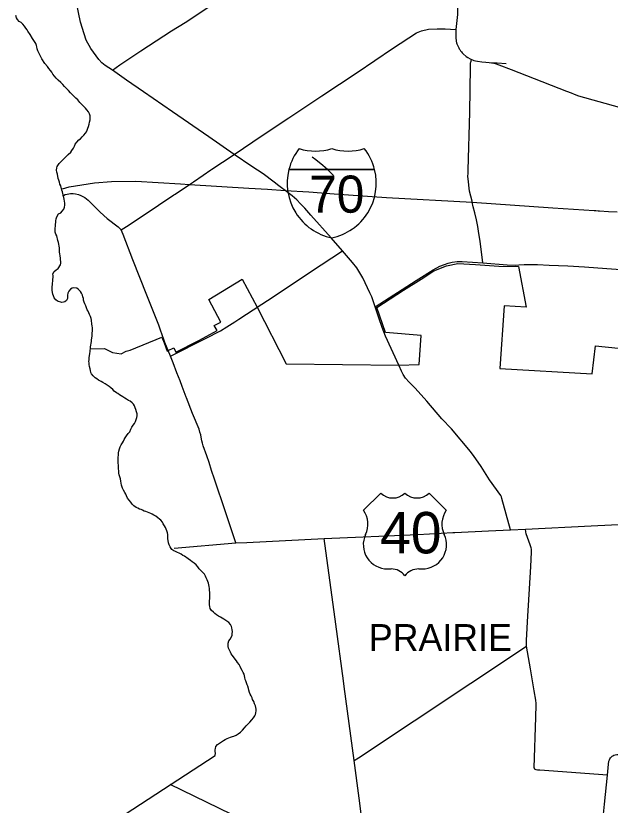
# Model space of a CAD drawing. Extents: x 1755200 to 1902939, y 644115 to 788070.
# Drawn here: x 1756901 to 1776912, y 701476 to 728043 of the extents above; entities that cross this region are included whole.
import ezdxf

# ---------------------------------------------------------------- set-up
doc = ezdxf.new("R2010")
doc.units = 0
for name, color, linetype in [('GM_X_County', 7, 'Continuous'), ('GM_X_County_Road', 7, 'Continuous'), ('GM_X_Interstate_Route', 7, 'Continuous'), ('GM_X_Interstate_Shield', 7, 'Continuous'), ('GM_X_Township', 7, 'Continuous'), ('GM_X_Township_Road', 7, 'Continuous'), ('GM_X_Township_Text', 7, 'Continuous'), ('GM_X_US_Route', 7, 'Continuous'), ('GM_X_US_Shield', 7, 'Continuous')]:
    doc.layers.add(name, color=color, linetype=linetype)

msp = doc.modelspace()

# ---------------------------------------------------------------- linework, layer by layer
at = {"layer": 'GM_X_County'}
msp.add_lwpolyline([(1759102, 700215), (1763614, 703154), (1763629, 703222), (1763617, 703283), (1763616, 703335), (1763624, 703387), (1763640, 703451), (1763691, 703517), (1763762, 703565), (1763830, 703611), (1763897, 703653), (1763952, 703683), (1764018, 703717), (1764071, 703745), (1764125, 703762), (1764195, 703784), (1764246, 703802), (1764320, 703836), (1764391, 703878), (1764462, 703938), (1764529, 704006), (1764599, 704075), (1764662, 704149), (1764719, 704213), (1764784, 704273), (1764848, 704345), (1764905, 704417), (1764948, 704482), (1764966, 704532), (1764983, 704588), (1764989, 704656), (1764993, 704708), (1764986, 704761), (1764968, 704815), (1764934, 704883), (1764909, 704966), (1764875, 705036), (1764859, 705087), (1764825, 705153), (1764796, 705217), (1764768, 705274), (1764746, 705348), (1764732, 705409), (1764713, 705477), (1764691, 705531), (1764669, 705594), (1764641, 705656), (1764626, 705706), (1764606, 705775), (1764602, 705825), (1764585, 705891), (1764557, 705944), (1764521, 706012), (1764477, 706093), (1764449, 706147), (1764420, 706208), (1764368, 706280), (1764330, 706337), (1764290, 706387), (1764228, 706470), (1764190, 706522), (1764156, 706575), (1764125, 706625), (1764091, 706695), (1764065, 706766), (1764053, 706820), (1764046, 706870), (1764050, 706933), (1764077, 707009), (1764113, 707061), (1764160, 707141), (1764180, 707193), (1764189, 707243), (1764193, 707320), (1764186, 707380), (1764174, 707440), (1764160, 707491), (1764132, 707555), (1764072, 707622), (1764008, 707666), (1763904, 707739), (1763854, 707765), (1763790, 707800), (1763724, 707840), (1763656, 707887), (1763602, 707929), (1763552, 707972), (1763490, 708032), (1763444, 708099), (1763428, 708159), (1763421, 708221), (1763421, 708288), (1763423, 708354), (1763428, 708436), (1763430, 708509), (1763433, 708579), (1763429, 708647), (1763424, 708699), (1763418, 708774), (1763410, 708838), (1763387, 708943), (1763367, 709005), (1763347, 709059), (1763314, 709130), (1763290, 709180), (1763250, 709247), (1763198, 709305), (1763146, 709366), (1763078, 709432), (1763028, 709501), (1762974, 709561), (1762910, 709620), (1762844, 709666), (1762778, 709711), (1762706, 709763), (1762580, 709854), (1762528, 709883), (1762468, 709921), (1762400, 709958), (1762346, 709984), (1762277, 710011), (1762227, 710033), (1762157, 710083), (1762134, 710119), (1762101, 710170), (1762068, 710241), (1762046, 710309), (1762028, 710387), (1762023, 710440), (1762021, 710504), (1762017, 710584), (1762006, 710637), (1761984, 710709), (1761964, 710767), (1761938, 710818), (1761903, 710882), (1761865, 710948), (1761839, 710999), (1761787, 711065), (1761735, 711106), (1761683, 711150), (1761613, 711203), (1761543, 711241), (1761493, 711268), (1761443, 711292), (1761392, 711310), (1761340, 711335), (1761274, 711357), (1761224, 711377), (1761172, 711402), (1761118, 711422), (1761064, 711444), (1761013, 711467), (1760949, 711493), (1760879, 711548), (1760821, 711606), (1760775, 711673), (1760715, 711743), (1760666, 711814), (1760630, 711888), (1760600, 711941), (1760570, 711999), (1760522, 712078), (1760489, 712144), (1760463, 712241), (1760447, 712311), (1760438, 712381), (1760424, 712456), (1760402, 712524), (1760383, 712592), (1760371, 712655), (1760365, 712705), (1760362, 712813), (1760360, 712870), (1760359, 712924), (1760353, 712990), (1760349, 713052), (1760352, 713121), (1760352, 713187), (1760357, 713261), (1760361, 713333), (1760371, 713392), (1760394, 713464), (1760415, 713534), (1760449, 713602), (1760490, 713674), (1760524, 713728), (1760553, 713780), (1760587, 713836), (1760628, 713908), (1760689, 713986), (1760739, 714046), (1760774, 714126), (1760813, 714195), (1760851, 714265), (1760892, 714317), (1760930, 714393), (1760957, 714453), (1760980, 714523), (1760984, 714585), (1760982, 714647), (1760969, 714720), (1760943, 714788), (1760923, 714853), (1760902, 714911), (1760861, 714970), (1760820, 715018), (1760750, 715068), (1760691, 715099), (1760623, 715141), (1760573, 715171), (1760503, 715218), (1760453, 715254), (1760393, 715291), (1760341, 715327), (1760291, 715352), (1760217, 715414), (1760165, 715465), (1760097, 715527), (1760045, 715566), (1759979, 715614), (1759908, 715655), (1759836, 715697), (1759770, 715737), (1759686, 715784), (1759624, 715827), (1759574, 715859), (1759502, 715923), (1759450, 715990), (1759426, 716042), (1759412, 716103), (1759401, 716163), (1759387, 716235), (1759373, 716302), (1759366, 716358), (1759364, 716412), (1759366, 716468), (1759375, 716540), (1759385, 716599), (1759398, 716677), (1759404, 716741), (1759409, 716793), (1759413, 716829), (1759415, 716843), (1759421, 716902), (1759430, 716954), (1759438, 717020), (1759446, 717080), (1759453, 717140), (1759461, 717199), (1759470, 717269), (1759472, 717325), (1759476, 717377), (1759479, 717429), (1759481, 717482), (1759479, 717540), (1759474, 717604), (1759466, 717662), (1759447, 717795), (1759435, 717861), (1759421, 717921), (1759388, 717992), (1759358, 718046), (1759332, 718099), (1759308, 718149), (1759280, 718215), (1759257, 718280), (1759227, 718348), (1759203, 718406), (1759185, 718475), (1759176, 718525), (1759158, 718589), (1759144, 718640), (1759110, 718712), (1759082, 718762), (1759017, 718835), (1758954, 718879), (1758850, 718888), (1758798, 718872), (1758747, 718844), (1758684, 718774), (1758658, 718712), (1758647, 718638), (1758647, 718586), (1758647, 718534), (1758609, 718457), (1758556, 718416), (1758505, 718403), (1758446, 718392), (1758310, 718440), (1758246, 718485), (1758197, 718550), (1758166, 718615), (1758143, 718677), (1758136, 718734), (1758125, 718804), (1758126, 718858), (1758129, 718926), (1758134, 718995), (1758139, 719047), (1758144, 719113), (1758151, 719183), (1758158, 719233), (1758161, 719295), (1758152, 719364), (1758191, 719435), (1758262, 719497), (1758329, 719540), (1758402, 719659), (1758412, 719713), (1758413, 719767), (1758411, 719836), (1758405, 719890), (1758392, 719966), (1758382, 720032), (1758376, 720089), (1758369, 720189), (1758367, 720239), (1758362, 720294), (1758350, 720360), (1758338, 720410), (1758316, 720478), (1758278, 720632), (1758249, 720699), (1758230, 720764), (1758227, 720830), (1758228, 720896), (1758235, 720964), (1758242, 721030), (1758249, 721081), (1758254, 721145), (1758261, 721211), (1758280, 721277), (1758339, 721373), (1758416, 721408), (1758464, 721473), (1758513, 721533), (1758541, 721597), (1758551, 721667), (1758551, 721737), (1758541, 721808), (1758533, 721866), (1758523, 721922), (1758501, 721990), (1758497, 722012), (1758483, 722064), (1758471, 722123), (1758452, 722179), (1758441, 722219), (1758412, 722319), (1758388, 722379), (1758374, 722445), (1758352, 722512), (1758330, 722572), (1758309, 722714), (1758284, 722778), (1758277, 722849), (1758280, 722921), (1758297, 722975), (1758364, 723076), (1758425, 723140), (1758483, 723200), (1758538, 723246), (1758609, 723314), (1758669, 723376), (1758750, 723448), (1758793, 723508), (1758842, 723584), (1758878, 723652), (1758905, 723718), (1758954, 723794), (1759024, 723866), (1759075, 723906), (1759140, 723968), (1759188, 724020), (1759249, 724088), (1759277, 724140), (1759304, 724192), (1759330, 724258), (1759351, 724322), (1759373, 724400), (1759388, 724468), (1759400, 724539), (1759407, 724625), (1759401, 724677), (1759385, 724743), (1759350, 724812), (1759288, 724874), (1759246, 724929), (1759178, 724999), (1759114, 725070), (1759052, 725130), (1758986, 725209), (1758926, 725270), (1758856, 725342), (1758804, 725399), (1758746, 725453), (1758676, 725526), (1758608, 725600), (1758544, 725659), (1758480, 725725), (1758416, 725802), (1758327, 725881), (1758262, 725942), (1758205, 726013), (1758152, 726080), (1758115, 726141), (1758068, 726206), (1758015, 726273), (1757963, 726333), (1757884, 726434), (1757777, 726589), (1757719, 726711), (1757643, 726864), (1757621, 726934), (1757614, 726993), (1757601, 727043), (1757573, 727111), (1757532, 727178), (1757462, 727283), (1757389, 727408), (1757310, 727522), (1757280, 727574), (1757243, 727626), (1757194, 727695), (1757135, 727758), (1757080, 727813), (1757014, 727852), (1756959, 727917), (1756928, 727976), (1756901, 728049)], dxfattribs=at)
at = {"layer": 'GM_X_County_Road'}
for points in [[(1771794, 729168), (1771770, 728090), (1771716, 727585), (1771714, 727532)], [(1764253, 723376), (1763399, 723968), (1762182, 724816), (1761195, 725480), (1760624, 725875), (1760154, 726216), (1759905, 726375), (1759797, 726464), (1759699, 726575), (1759604, 726696), (1759424, 726937), (1759271, 727226), (1759203, 727430), (1759078, 727831), (1758945, 728479)], [(1764253, 723376), (1765199, 724019), (1766094, 724606), (1767200, 725351), (1768394, 726135), (1769578, 726938), (1770391, 727467), (1770559, 727542), (1770789, 727597), (1771082, 727607), (1771355, 727601), (1771716, 727585)], [(1771714, 727532), (1771712, 727461), (1771711, 727391), (1771715, 727313), (1771728, 727189), (1771737, 727138), (1771753, 727096), (1771790, 727007), (1771815, 726960), (1771831, 726931), (1771848, 726903), (1771871, 726869), (1771900, 726830), (1771930, 726795), (1771960, 726761), (1772057, 726675), (1772118, 726634), (1772197, 726591), (1772247, 726569), (1772275, 726558)], [(1772207, 726312), (1772208, 726404), (1772210, 726460), (1772215, 726487), (1772228, 726516), (1772247, 726569)], [(1772275, 726558), (1772320, 726541), (1772375, 726527), (1772446, 726513), (1772594, 726496), (1772727, 726487), (1772832, 726475), (1772915, 726460), (1772936, 726456), (1773036, 726433), (1773161, 726391), (1773574, 726231), (1774090, 726031)], [(1772127, 722735), (1772131, 722845), (1772189, 724803), (1772207, 726312)], [(1774090, 726031), (1775440, 725510), (1775595, 725449), (1775701, 725407), (1775843, 725352), (1777898, 724773), (1778050, 724736)], [(1763498, 722877), (1763860, 723116), (1764253, 723376)], [(1765848, 722257), (1765757, 722324), (1765598, 722443), (1765228, 722720), (1764846, 722976), (1764253, 723376)], [(1767591, 722664), (1767519, 722745), (1767392, 722870), (1767234, 723005), (1767000, 723190), (1766875, 723283)], [(1762882, 722459), (1763205, 722681), (1763466, 722856), (1763498, 722877)], [(1772261, 721801), (1772179, 722137), (1772160, 722240), (1772136, 722460), (1772124, 722645), (1772127, 722735)], [(1762264, 722044), (1762744, 722369), (1762815, 722413), (1762882, 722459)], [(1766564, 721638), (1766491, 721719), (1766365, 721844), (1766206, 721979), (1765972, 722164), (1765848, 722257)], [(1758503, 721998), (1758566, 722023), (1758626, 722040), (1758689, 722052), (1758747, 722059), (1758833, 722063), (1758912, 722053), (1759007, 722029), (1759089, 722000), (1759160, 721961), (1759226, 721925), (1759336, 721834), (1759397, 721778), (1759740, 721434), (1759978, 721223), (1760347, 720936), (1760447, 720841)], [(1760447, 720841), (1760449, 720839), (1760633, 720954), (1761188, 721317), (1762226, 722018), (1762264, 722044)], [(1769809, 716261), (1769796, 716289), (1769344, 717262), (1769230, 717555), (1769119, 717879), (1768999, 718250), (1768883, 718579), (1768824, 718722), (1768580, 719220), (1768383, 719563), (1768236, 719745), (1767894, 720130), (1767516, 720568), (1766832, 721336), (1766628, 721567), (1766564, 721638)], [(1772492, 720721), (1772459, 720947), (1772412, 721180), (1772353, 721415), (1772303, 721618), (1772269, 721770), (1772261, 721801)], [(1761713, 717627), (1761317, 718643), (1760845, 719828), (1760514, 720686), (1760449, 720839)], [(1772622, 719729), (1772529, 720458), (1772492, 720721)], [(1765016, 718231), (1765025, 718236), (1765527, 718566), (1766826, 719421), (1767894, 720130)], [(1768999, 718250), (1770380, 719133), (1770957, 719492), (1771175, 719614), (1771329, 719676), (1771459, 719718), (1771593, 719748), (1771756, 719773), (1771924, 719777), (1772622, 719729), (1773445, 719658), (1773708, 719650), (1773839, 719658), (1774017, 719675), (1774154, 719677), (1774392, 719672), (1774468, 719669)], [(1774468, 719669), (1774852, 719655), (1775486, 719628), (1776050, 719595), (1776800, 719535), (1777265, 719506)], [(1762112, 716585), (1763282, 717180), (1763789, 717440), (1764009, 717570), (1764270, 717740), (1764407, 717834), (1764663, 718002), (1764896, 718152), (1765016, 718231)], [(1761878, 717178), (1761844, 717272), (1761764, 717495), (1761713, 717627)], [(1762032, 716782), (1761923, 717049), (1761878, 717178)], [(1762642, 715203), (1762503, 715565), (1762429, 715756), (1762323, 716029), (1762196, 716359), (1762112, 716585), (1762035, 716774), (1762032, 716782)], [(1773553, 710745), (1773265, 711797), (1773256, 711849), (1773224, 711901), (1772851, 712424), (1772563, 712870), (1772311, 713244), (1772269, 713298), (1772206, 713381), (1771572, 714137), (1771246, 714484), (1770736, 715072), (1770341, 715507), (1770139, 715714), (1770018, 715844), (1769944, 715974), (1769890, 716083), (1769809, 716261)], [(1764309, 710302), (1763930, 711446), (1763837, 711717), (1763717, 712074), (1763587, 712450), (1763492, 712738), (1763407, 713006), (1763337, 713229), (1763210, 713571), (1763184, 713662), (1763165, 713740), (1763144, 713859), (1763129, 713944), (1763101, 714035), (1763073, 714126), (1762852, 714654), (1762647, 715190), (1762642, 715203)], [(1776818, 702492), (1774543, 702655), (1774461, 702658), (1774417, 702666), (1774400, 702673), (1774382, 702683), (1774363, 702704), (1774359, 702721), (1774356, 702738), (1774404, 704443), (1774416, 704859), (1774415, 704899), (1774404, 705016), (1774351, 705325), (1774225, 706068), (1774099, 706832), (1774092, 706909), (1774093, 707017), (1774137, 707851), (1774163, 708194), (1774234, 709514), (1774263, 709994), (1774263, 710046), (1774260, 710095), (1774250, 710142), (1774217, 710241), (1774087, 710608), (1774066, 710680), (1774058, 710769)], [(1769211, 696603), (1769207, 696674), (1769146, 697650), (1769123, 697982), (1769092, 698322), (1769069, 698471), (1769011, 698712), (1768797, 699571), (1768694, 699972), (1768678, 700045), (1768665, 700116), (1768455, 701718), (1768288, 702977), (1767960, 705470), (1767928, 705663), (1767674, 707564), (1767277, 710453)], [(1776685, 701171), (1776719, 701507), (1776818, 702492), (1776856, 702853), (1776869, 702957), (1776884, 703001), (1776904, 703039), (1776926, 703068), (1776954, 703101), (1776979, 703122), (1777002, 703137), (1777038, 703156), (1777081, 703171), (1777131, 703182), (1777204, 703183), (1777371, 703181)]]:
    msp.add_lwpolyline(points, dxfattribs=at)
at = {"layer": 'GM_X_Interstate_Route'}
for points in [[(1758469, 722217), (1758703, 722287), (1759549, 722416), (1760123, 722463), (1760938, 722480), (1762441, 722391), (1762744, 722369), (1764742, 722242), (1765370, 722213), (1765972, 722164), (1766767, 722119), (1767622, 722052), (1769376, 721928), (1772269, 721770), (1774978, 721575), (1776374, 721488), (1776427, 721485), (1776503, 721480)], [(1776503, 721480), (1776556, 721476)], [(1776556, 721476), (1776858, 721457), (1777140, 721440)]]:
    msp.add_lwpolyline(points, dxfattribs=at)
at = {"layer": 'GM_X_Interstate_Shield'}
for p, q in [((1766095, 722869), (1768980, 722869)), ((1768980, 722869), (1766095, 722869)), ((1768980, 722869), (1766095, 722869))]:
    msp.add_line(p, q, dxfattribs=at)
for centre, start, end in [((1767913, 722409), 141.669, 165.8066), ((1766990, 725365), 253.0091, 286.9909), ((1768086, 725365), 253.0091, 286.9909), ((1767163, 722409), 14.1934, 38.331), ((1767913, 722409), 165.8066, 258.463), ((1767163, 722409), 281.537, 14.1934)]:
    msp.add_arc(centre, 1875, start, end, dxfattribs=at)
at = {"layer": 'GM_X_Township'}
for points in [[(1759413, 716829), (1759887, 716844), (1760162, 716710), (1760451, 716669), (1760614, 716757), (1760752, 716794), (1761821, 717229), (1761896, 717034), (1762001, 716760), (1762035, 716774), (1762227, 716867), (1762287, 716719), (1763068, 717118), (1763685, 717447), (1763580, 717618), (1763806, 717731), (1763400, 718493), (1764517, 719183), (1765025, 718236), (1766008, 716330), (1769796, 716289), (1770484, 716305), (1770543, 717284), (1769347, 717380), (1769050, 718225), (1769957, 718811), (1770547, 719179), (1770974, 719455), (1771401, 719630), (1771785, 719706), (1772380, 719672), (1773166, 719622), (1773827, 719605), (1774078, 718233), (1773342, 718283), (1773191, 716175), (1776303, 715995), (1776417, 716930), (1778382, 716739)], [(1794587, 689062), (1792546, 689167), (1791461, 689213), (1784810, 689542), (1784632, 689548), (1783167, 689596), (1782688, 689618), (1780628, 689706), (1776861, 692396), (1776156, 692877), (1775926, 693071), (1769123, 697982), (1765814, 700371), (1762103, 702170)]]:
    msp.add_lwpolyline(points, dxfattribs=at)
at = {"layer": 'GM_X_Township_Road'}
for points in [[(1760154, 726216), (1760398, 726396), (1761114, 726868), (1762144, 727537), (1762606, 727820), (1763836, 728646)], [(1772936, 726456), (1772971, 726464), (1773051, 726458), (1773111, 726455), (1773410, 726433)], [(1768288, 702977), (1768433, 703067), (1774099, 706832)]]:
    msp.add_lwpolyline(points, dxfattribs=at)
at = {"layer": 'GM_X_US_Route'}
for points in [[(1764674, 710320), (1767277, 710453), (1770437, 710588), (1771611, 710654), (1771683, 710653), (1772818, 710706), (1773553, 710745), (1774058, 710769), (1776274, 710876), (1778328, 710978)], [(1762237, 710121), (1764309, 710302), (1764674, 710320)]]:
    msp.add_lwpolyline(points, dxfattribs=at)
at = {"layer": 'GM_X_US_Shield'}
for p, q in [((1769188, 711981), (1768608, 711401)), ((1771392, 711401), (1770812, 711981)), ((1769420, 709429), (1769536, 709429)), ((1770464, 709429), (1770580, 709429))]:
    msp.add_line(p, q, dxfattribs=at)
for centre, radius, start, end in [((1769594, 712395), 580, 225.573, 314.427), ((1770406, 712395), 580, 225.573, 314.427), ((1767943, 710935), 812, 334.5471, 35.0009), ((1772058, 710935), 812, 144.9991, 205.4529), ((1769411, 710241), 812, 154.8319, 270.6383), ((1770589, 710241), 812, 269.3617, 25.1681), ((1769536, 708848), 580, 36.8699, 90), ((1770464, 708848), 580, 90, 143.1301)]:
    msp.add_arc(centre, radius, start, end, dxfattribs=at)

# ---------------------------------------------------------------- texts
at = {"layer": 'GM_X_Interstate_Shield'}
msp.add_text('70', height=1250, dxfattribs=at).set_placement((1766775, 721416))
at = {"layer": 'GM_X_Township_Text'}
msp.add_text('PRAIRIE', height=900, rotation=0, dxfattribs=at).set_placement((1768786, 706670))
at = {"layer": 'GM_X_US_Shield'}
msp.add_text('40', height=1392.2, dxfattribs=at).set_placement((1769164, 709951))

doc.saveas('drawing.dxf')
